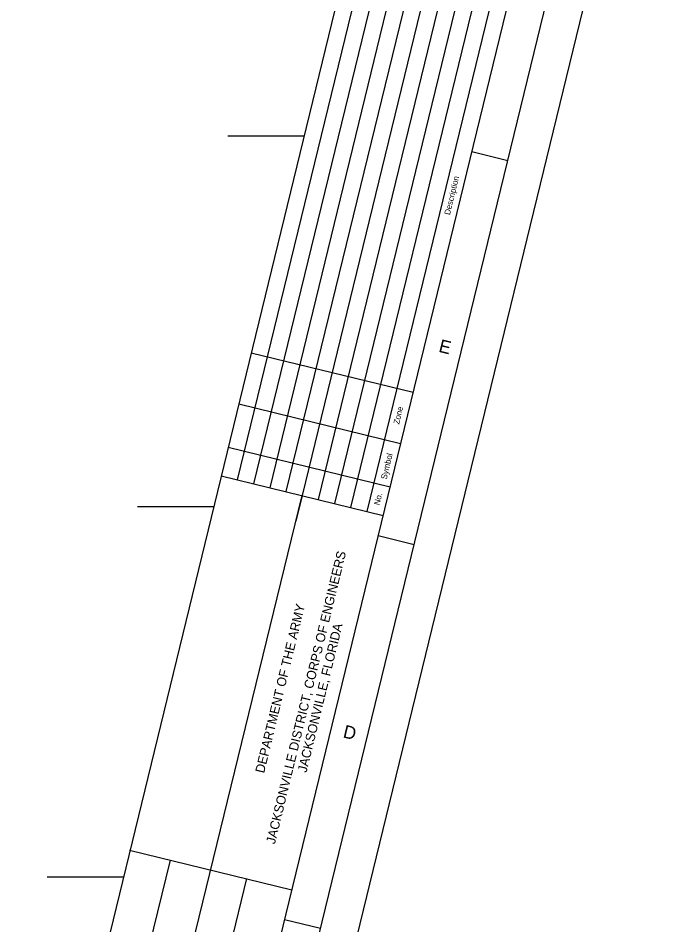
# Model space of a CAD drawing. Extents: x 406346 to 411426, y 1189267 to 1193612.
# Drawn here: x 410567 to 411426, y 1190935 to 1192159 of the extents above; entities that cross this region are included whole.
import ezdxf

# ---------------------------------------------------------------- set-up
doc = ezdxf.new("R2010")
doc.units = 0
for name, color, linetype in [('G-ANNO-NPLT', 7, 'Continuous'), ('G-ANNO-TEXT-TTLB', 7, 'Continuous'), ('G-ANNO-TTLB', 7, 'Continuous'), ('V-TOPO-COOR-STAT', 7, 'Continuous')]:
    doc.layers.add(name, color=color, linetype=linetype)

msp = doc.modelspace()

# ---------------------------------------------------------------- linework, layer by layer
at = {"layer": 'G-ANNO-NPLT'}
msp.add_lwpolyline([(407151.7, 1193612.5), (411426.4, 1192570), (410620.9, 1189266.8), (406346.2, 1190309.3)], close=True, dxfattribs=at)
at = {"layer": 'G-ANNO-TTLB'}
for p, q in [((411086.9, 1192549.9), (410328.8, 1189441)), ((411061.2, 1192349.9), (410862.7, 1191535.9)), ((411083, 1192344.6), (410884.5, 1191530.5)), ((411104.9, 1192339.3), (410906.4, 1191525.2)), ((411126.8, 1192333.9), (410928.2, 1191519.9)), ((411148.6, 1192328.6), (410950.1, 1191514.5)), ((411170.5, 1192323.3), (410971.9, 1191509.2)), ((411192.3, 1192317.9), (410993.8, 1191503.9)), ((411214.2, 1192312.6), (411015.7, 1191498.5)), ((411236.1, 1192307.3), (411037.5, 1191493.2)), ((411227.7, 1191966.4), (411179.2, 1191978.2)), ((410881.5, 1191707.3), (411100.1, 1191654)), ((410864.6, 1191638.2), (411083.2, 1191584.8)), ((410850.4, 1191579.9), (411069, 1191526.5)), ((410841, 1191541.1), (411059.6, 1191487.8)), ((410746, 1190679.6), (410950.3, 1191514.5)), ((410950.3, 1191514.5), (410941.9, 1191480.1)), ((411101.4, 1191448.3), (411052.8, 1191460.1)), ((410717, 1191036.2), (410936.4, 1190982.7)), ((410691.6, 1190692.9), (410772.4, 1191022.7)), ((410875.2, 1190997.7), (410794.7, 1190667.7)), ((410975, 1190930.2), (410926.5, 1190942))]:
    msp.add_line(p, q, dxfattribs=at)
for points in [[(406406.6, 1190346), (410584.1, 1189327.2), (411366, 1192533.3), (407188.5, 1193552.1)], [(411305.6, 1192496.5), (407298, 1193473.9), (406539.9, 1190365), (410547.4, 1189387.7)]]:
    msp.add_lwpolyline(points, close=True, dxfattribs=at)
at = {"layer": 'V-TOPO-COOR-STAT'}
for p, q in [((410849.9, 1192000), (410952.9, 1192000)), ((410728, 1191500), (410830.9, 1191500)), ((410606, 1191000), (410709, 1191000))]:
    msp.add_line(p, q, dxfattribs=at)

# ---------------------------------------------------------------- texts
at = {"layer": 'G-ANNO-TEXT-TTLB'}
for s, height, p in [('Description', 8, (411149.7, 1191892.7)), ('Zone', 8, (411081.1, 1191610.2)), ('Symbol', 8, (411064.2, 1191535.8)), ('No.', 8, (411054.6, 1191501)), ('JACKSONVILLE DISTRICT, CORPS OF ENGINEERS', 12.5, (410913.5, 1191043.6)), ('DEPARTMENT OF THE ARMY', 12.5, (410898.8, 1191139.2)), ('JACKSONVILLE, FLORIDA', 12.5, (410956.1, 1191140.1))]:
    msp.add_text(s, height=height, rotation=76.2946, dxfattribs=at).set_placement(p)
at = {"layer": 'G-ANNO-TTLB'}
for s, p in [('E', (411133.6, 1191708.7)), ('D', (411004.4, 1191188.4))]:
    msp.add_text(s, height=17.5, rotation=346.2946, dxfattribs=at).set_placement(p)

doc.saveas('drawing.dxf')
